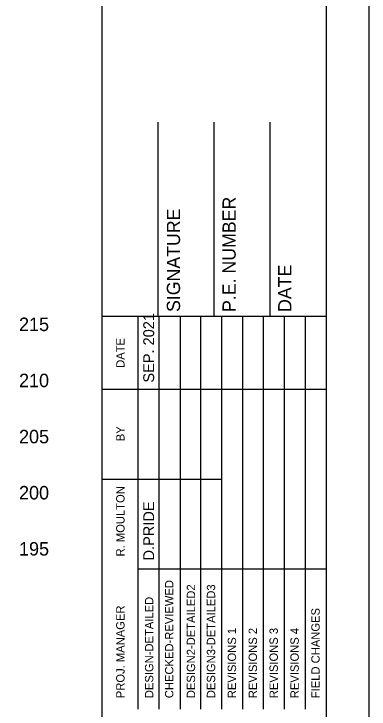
# Model space of a CAD drawing. Extents: x 852087 to 852430, y 366898 to 367118.
# Drawn here: x 852395.1 to 852426.7, y 366994.5 to 367056.4 of the extents above; entities that cross this region are included whole.
import ezdxf

# ---------------------------------------------------------------- set-up
doc = ezdxf.new("R2010")
doc.units = 0
for name, color, linetype in [('BORDER', 7, 'Continuous'), ('H_V ANNOTATION', 7, 'Continuous'), ('PLOT BOUNDARY', 7, 'Continuous')]:
    doc.layers.add(name, color=color, linetype=linetype)

msp = doc.modelspace()

# ---------------------------------------------------------------- linework, layer by layer
at = {"layer": 'BORDER'}
for p, q in [((852402.931, 366904.473), (852402.931, 367114.473)), ((852407.931, 367029.479), (852407.931, 367046.774)), ((852412.931, 367029.479), (852412.931, 367046.774)), ((852417.931, 367029.479), (852417.931, 367046.774)), ((852402.931, 367029.479), (852422.931, 367029.479))]:
    msp.add_line(p, q, dxfattribs=at)
msp.add_lwpolyline([(852102.931, 366904.473), (852422.931, 366904.473), (852422.931, 367114.473), (852102.931, 367114.473)], close=True, dxfattribs=at)
for points in [[(852406.161, 367022.979), (852406.161, 367029.479)], [(852408.026, 366994.485), (852408.026, 367029.479)], [(852409.889, 367029.479), (852409.889, 366994.485)], [(852411.753, 366994.485), (852411.753, 367029.479)], [(852413.616, 366994.485), (852413.616, 367029.479)], [(852415.479, 366994.485), (852415.479, 367029.479)], [(852417.343, 366994.485), (852417.343, 367029.479)], [(852419.206, 366994.485), (852419.206, 367029.479)], [(852421.07, 366994.485), (852421.07, 367029.479)], [(852406.163, 366994.485), (852406.163, 367028.067)], [(852402.931, 367022.979), (852422.931, 367022.979)], [(852402.931, 367014.979), (852406.163, 367014.979)], [(852406.161, 367014.979), (852413.614, 367014.979)], [(852406.161, 367006.979), (852422.931, 367006.979)]]:
    msp.add_lwpolyline(points, dxfattribs=at)
at = {"layer": 'PLOT BOUNDARY'}
msp.add_lwpolyline([(852086.744, 366898.355), (852426.744, 366898.355), (852426.744, 367118.355), (852086.744, 367118.355)], close=True, dxfattribs=at)

# ---------------------------------------------------------------- texts
at = {"layer": 'BORDER'}
for s, height, p in [('P.E. NUMBER', 1.1811, (852414.853, 367029.863)), ('SIGNATURE', 1.1811, (852409.892, 367029.863)), ('DATE', 1.1811, (852419.813, 367029.863)), ('SEP. 2021', 0.9691, (852407.577, 367023.57)), ('DATE', 0.7428, (852404.94, 367024.89)), ('BY', 0.7428, (852404.94, 367018.349)), ('R. MOULTON', 0.7455, (852404.94, 367008.084)), ('D.PRIDE', 0.9691, (852407.577, 367007.725)), ('CHECKED-REVIEWED', 0.7455, (852409.293, 366995.455)), ('DESIGN2-DETAILED2', 0.7455, (852411.231, 366995.455)), ('DESIGN3-DETAILED3', 0.7455, (852413.02, 366995.455)), ('DESIGN-DETAILED', 0.7455, (852407.504, 366995.455)), ('PROJ. MANAGER', 0.7455, (852404.94, 366995.455)), ('FIELD CHANGES', 0.7455, (852422.337, 366995.455)), ('REVISIONS 1', 0.7455, (852414.883, 366995.455)), ('REVISIONS 2', 0.7455, (852416.747, 366995.455)), ('REVISIONS 3', 0.7455, (852418.61, 366995.455)), ('REVISIONS 4', 0.7455, (852420.473, 366995.455))]:
    msp.add_text(s, height=height, rotation=90, dxfattribs=at).set_placement(p)
at = {"layer": 'H_V ANNOTATION'}
for s, p in [('215', (852395.531, 367028.161)), ('210', (852395.531, 367023.161)), ('205', (852395.531, 367018.161)), ('200', (852395.531, 367013.161)), ('195', (852395.531, 367008.161))]:
    msp.add_text(s, height=1.2, dxfattribs=at).set_placement(p)

doc.saveas('drawing.dxf')
